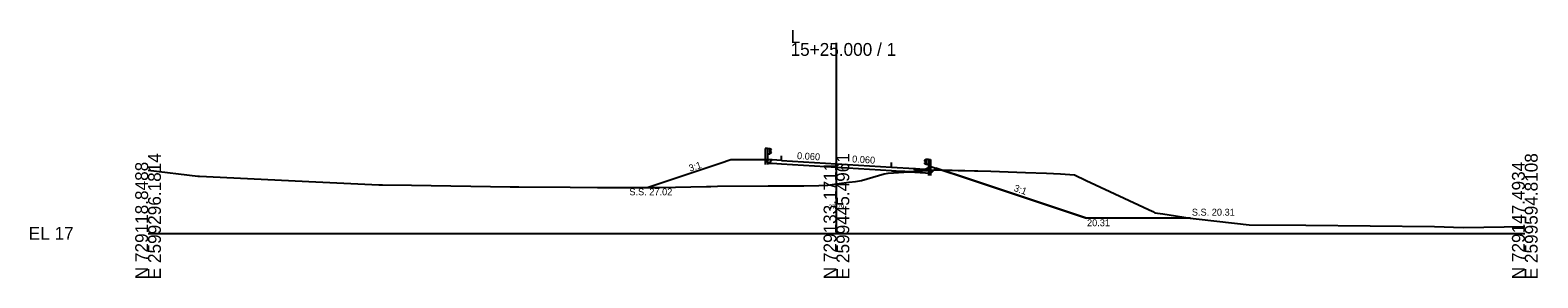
# Model space of a CAD drawing. Extents: x -26 to 3303, y -10 to 9555.
# Drawn here: x 974.3 to 1302.8, y 490.3 to 544.3 of the extents above; entities that cross this region are included whole.
import ezdxf

# ---------------------------------------------------------------- set-up
doc = ezdxf.new("R2010")
doc.units = 0
for name, color, linetype in [('Exist Cross Section Cell', 7, 'Continuous'), ('Exist XS Center Line Elevation Label', 7, 'Continuous'), ('Exist XS Ground Line', 7, 'Continuous'), ('Prop XS Ditch Slope Text', 7, 'Continuous'), ('Prop XS Ditch Standard Text', 7, 'Continuous'), ('Prop XS Dump Level', 7, 'Continuous'), ('Prop XS Earthwork Shape', 7, 'Continuous'), ('Prop XS EOT Tick Mark', 7, 'Continuous'), ('Prop XS Finish Grade', 7, 'Continuous'), ('Prop XS Finish Grade Earthwork', 7, 'Continuous'), ('Prop XS Finish Grade Paved Shoulder', 7, 'Continuous'), ('Prop XS Finish Grade Pavement', 7, 'Continuous'), ('Prop XS Pvmt Edge Slope', 7, 'Continuous'), ('Prop XS SE Text', 7, 'Continuous'), ('Prop XS Side Slope Text', 7, 'Continuous'), ('Prop XS SS Elevation Text', 7, 'Continuous'), ('Prop XS Subgrade Earthwork', 7, 'Continuous'), ('Typical Curb CELL', 7, 'Continuous'), ('Typical Guardrail CELL', 7, 'Continuous')]:
    doc.layers.add(name, color=color, linetype=linetype)

msp = doc.modelspace()

# ---------------------------------------------------------------- linework, layer by layer
at = {"layer": 'Exist Cross Section Cell'}
for p, q in [((1150, 500), (1150, 541.5)), ((1000, 500), (1150, 500)), ((1150, 500), (1300, 500))]:
    msp.add_line(p, q, dxfattribs=at)
at = {"layer": 'Exist XS Ground Line'}
msp.add_lwpolyline([(1000, 513.8), (1010.85, 512.5), (1011.23, 512.49), (1027.66, 511.68), (1035.06, 511.29), (1050.25, 510.61), (1051.09, 510.57), (1057.39, 510.53), (1078.88, 510.18), (1080, 510.16), (1080.79, 510.13), (1091.99, 510.06), (1097.91, 510.02), (1098.5, 510.02), (1099.09, 510.02), (1111.52, 510.01), (1121.72, 510.21), (1122.66, 510.25), (1124.1, 510.3), (1135.12, 510.33), (1142.88, 510.33), (1146.13, 510.43), (1148.16, 510.54), (1150, 510.79), (1152.78, 511.18), (1154.12, 511.32), (1155.47, 511.51), (1160.41, 513.01), (1161.26, 513.12), (1164.65, 513.31), (1171.81, 513.83), (1172.37, 513.82), (1183.67, 513.56), (1191.22, 513.25), (1195.75, 513.15), (1198.83, 512.97), (1201.84, 512.76), (1204.4, 511.56), (1218.92, 504.74), (1219.4, 504.5), (1221.09, 504.23), (1227.1, 503.31), (1229.04, 503.08), (1239.92, 501.85), (1252.31, 501.78), (1280.31, 501.51), (1286.58, 501.25), (1300, 501.52)], dxfattribs=at)
at = {"layer": 'Prop XS Dump Level'}
for p, q in [((1138, 515.91), (1150, 515.19)), ((1150, 515.19), (1162, 514.47))]:
    msp.add_line(p, q, dxfattribs=at)
at = {"layer": 'Prop XS Earthwork Shape'}
for points in [[(1135.21, 515.25), (1134.43, 516.03), (1127, 516.03), (1124.64, 515.25), (1108.95, 510.01), (1111.52, 510.01), (1121.72, 510.21), (1122.66, 510.25), (1124.1, 510.3), (1135.12, 510.33), (1142.88, 510.33), (1146.13, 510.43), (1148.16, 510.54), (1150, 510.79), (1152.78, 511.18), (1154.12, 511.32), (1155.47, 511.51), (1160.41, 513.01), (1161.26, 513.12), (1164.65, 513.31), (1165.9, 513.4), (1164.89, 513.47), (1164, 513.52), (1162, 513.64), (1150, 514.36), (1138, 515.08), (1136, 515.2)], [(1135.21, 515.25), (1134.43, 516.03), (1127, 516.03), (1124.64, 515.25), (1108.95, 510.01), (1111.52, 510.01), (1121.72, 510.21), (1122.66, 510.25), (1124.1, 510.3), (1135.12, 510.33), (1142.88, 510.33), (1146.13, 510.43), (1148.16, 510.54), (1150, 510.79), (1152.78, 511.18), (1154.12, 511.32), (1155.47, 511.51), (1160.41, 513.01), (1161.26, 513.12), (1164.65, 513.31), (1165.9, 513.4), (1164.89, 513.47), (1164, 513.52), (1162, 513.64), (1150, 514.36), (1138, 515.08), (1136, 515.2)], [(1165.9, 513.4), (1170.56, 513.12), (1171.23, 513.79)], [(1165.9, 513.4), (1170.56, 513.12), (1171.23, 513.79)], [(1171.81, 513.83), (1172.37, 513.82), (1172.97, 513.81), (1171.68, 514.24), (1171.23, 513.79)], [(1171.81, 513.83), (1172.37, 513.82), (1172.97, 513.81), (1171.68, 514.24), (1171.23, 513.79)], [(1227.13, 503.31), (1204.46, 503.31), (1176.4, 512.66), (1172.97, 513.81), (1183.67, 513.56), (1191.22, 513.25), (1195.75, 513.15), (1198.83, 512.97), (1201.84, 512.76), (1204.4, 511.56), (1218.92, 504.74), (1219.4, 504.5), (1221.09, 504.23), (1227.1, 503.31)], [(1227.13, 503.31), (1204.46, 503.31), (1176.4, 512.66), (1172.97, 513.81), (1183.67, 513.56), (1191.22, 513.25), (1195.75, 513.15), (1198.83, 512.97), (1201.84, 512.76), (1204.4, 511.56), (1218.92, 504.74), (1219.4, 504.5), (1221.09, 504.23), (1227.1, 503.31)]]:
    msp.add_lwpolyline(points, close=True, dxfattribs=at)
at = {"layer": 'Prop XS EOT Tick Mark'}
for p, q in [((1138, 515.91), (1138, 516.91)), ((1162, 514.47), (1162, 515.47))]:
    msp.add_line(p, q, dxfattribs=at)
at = {"layer": 'Prop XS Finish Grade'}
for p, q in [((1136, 516.03), (1134.43, 516.03)), ((1170.03, 514.36), (1170.56, 514.61)), ((1170.56, 514.61), (1171.68, 514.24))]:
    msp.add_line(p, q, dxfattribs=at)
at = {"layer": 'Prop XS Finish Grade Earthwork'}
for p, q in [((1127, 516.03), (1124.64, 515.25)), ((1134.43, 516.03), (1127, 516.03)), ((1124.64, 515.25), (1108.95, 510.01)), ((1171.68, 514.24), (1176.4, 512.66)), ((1176.4, 512.66), (1204.46, 503.31)), ((1227.13, 503.31), (1204.46, 503.31))]:
    msp.add_line(p, q, dxfattribs=at)
at = {"layer": 'Prop XS Finish Grade Paved Shoulder'}
for p, q in [((1138, 515.91), (1136, 516.03)), ((1162, 514.47), (1167, 514.17))]:
    msp.add_line(p, q, dxfattribs=at)
at = {"layer": 'Prop XS Finish Grade Pavement'}
for p, q in [((1138, 515.91), (1150, 515.19)), ((1150, 515.19), (1162, 514.47))]:
    msp.add_line(p, q, dxfattribs=at)
at = {"layer": 'Prop XS Pvmt Edge Slope'}
for p, q in [((1135.21, 515.25), (1134.43, 516.03)), ((1136, 516.03), (1135.21, 515.25)), ((1170.01, 513.68), (1170.56, 513.12)), ((1170.56, 513.12), (1171.68, 514.24))]:
    msp.add_line(p, q, dxfattribs=at)
at = {"layer": 'Prop XS Subgrade Earthwork'}
for p, q in [((1135.21, 515.25), (1134.43, 516.03)), ((1136, 515.2), (1135.21, 515.25)), ((1138, 515.08), (1136, 515.2)), ((1150, 514.36), (1138, 515.08)), ((1162, 513.64), (1150, 514.36)), ((1162, 513.64), (1164, 513.52)), ((1164, 513.52), (1164.89, 513.47)), ((1164.89, 513.47), (1170.56, 513.12)), ((1170.56, 513.12), (1171.68, 514.24))]:
    msp.add_line(p, q, dxfattribs=at)
at = {"layer": 'Typical Curb CELL'}
for p, q in [((1166.99, 513.76), (1167, 514.16)), ((1170.01, 513.68), (1166.99, 513.76)), ((1167, 514.17), (1167, 514.17)), ((1167.01, 514.17), (1169.33, 514.03)), ((1167.23, 513.9), (1167.32, 514.02)), ((1167.35, 513.9), (1167.23, 513.9)), ((1167.32, 514.02), (1167.35, 513.9)), ((1167.99, 513.83), (1168.06, 513.94)), ((1168.16, 513.87), (1167.99, 513.83)), ((1168.06, 513.94), (1168.16, 513.87)), ((1168.48, 513.87), (1168.57, 513.99)), ((1168.6, 513.87), (1168.48, 513.87)), ((1168.57, 513.99), (1168.6, 513.87)), ((1169.24, 513.8), (1169.31, 513.91)), ((1169.41, 513.84), (1169.24, 513.8)), ((1169.31, 513.91), (1169.41, 513.84)), ((1169.33, 514.03), (1170.03, 514.36)), ((1169.83, 514.03), (1169.84, 513.94)), ((1169.98, 513.98), (1169.83, 514.03)), ((1169.84, 513.94), (1169.98, 513.98)), ((1170.01, 513.68), (1170.03, 514.36))]:
    msp.add_line(p, q, dxfattribs=at)
for centre in [(1167.09, 513.99), (1167.13, 514.12), (1167.49, 514.03), (1167.55, 513.85), (1167.6, 513.82), (1167.64, 513.94), (1167.71, 513.94), (1167.76, 513.97), (1167.81, 513.85), (1168, 513.89), (1168.21, 513.86), (1168.23, 513.91), (1168.24, 513.97), (1168.29, 513.83), (1168.39, 513.87), (1168.48, 513.88), (1168.6, 513.83), (1168.8, 513.82), (1168.85, 513.79), (1168.89, 513.91), (1169.01, 513.94), (1169.06, 513.82), (1169.25, 513.85), (1169.28, 513.75), (1169.46, 513.83), (1169.48, 513.88), (1169.73, 513.85), (1169.85, 513.79), (1169.95, 514.07)]:
    msp.add_circle(centre, 0.00802, dxfattribs=at)
msp.add_arc((1167.01, 514.16), 0.0104, 86.5213, 178.5693, dxfattribs=at)
at = {"layer": 'Typical Guardrail CELL'}
for p, q in [((1135, 518.52), (1134.5, 518.52)), ((1134.5, 518.52), (1134.5, 516.03)), ((1135, 516.03), (1134.5, 516.03)), ((1134.5, 516.03), (1134.5, 515.02)), ((1135, 518.52), (1135, 516.03)), ((1135, 518.52), (1135.5, 518.52)), ((1135, 517.36), (1135.5, 517.36)), ((1135, 516.03), (1135, 515.02)), ((1135.5, 518.52), (1135.5, 517.36)), ((1135.5, 518.52), (1135.79, 518.31)), ((1135.5, 517.98), (1135.79, 518.19)), ((1135.5, 517.94), (1135.5, 517.98)), ((1135.5, 517.94), (1135.5, 517.89)), ((1135.5, 517.89), (1135.79, 517.69)), ((1135.5, 517.36), (1135.79, 517.56)), ((1169.53, 516.14), (1169.24, 515.94)), ((1169.53, 515.61), (1169.24, 515.81)), ((1170.03, 516.14), (1169.53, 516.14)), ((1169.53, 516.14), (1169.53, 514.98)), ((1170.03, 516.14), (1170.03, 513.65)), ((1170.03, 516.14), (1170.53, 516.14)), ((1170.53, 516.14), (1170.53, 513.65)), ((1169.53, 515.51), (1169.24, 515.31)), ((1169.53, 514.98), (1169.24, 515.18)), ((1169.53, 515.56), (1169.53, 515.61)), ((1169.53, 515.56), (1169.53, 515.51)), ((1170.03, 514.98), (1169.53, 514.98)), ((1170.03, 513.65), (1170.53, 513.65)), ((1170.03, 513.65), (1170.03, 512.64)), ((1170.53, 513.65), (1170.53, 512.64))]:
    msp.add_line(p, q, dxfattribs=at)
for centre, start, end in [((1135.74, 518.25), 304.9888, 54.997), ((1135.74, 517.62), 304.9634, 54.9941), ((1169.29, 515.87), 125.003, 235.0112), ((1169.29, 515.25), 125.0059, 235.0366)]:
    msp.add_arc(centre, 0.0776, start, end, dxfattribs=at)

# ---------------------------------------------------------------- texts
at = {"layer": 'Exist Cross Section Cell'}
for s, p in [('L', (1140, 541.5)), ('15+25.000 / 1', (1140, 538.7)), ('EL 17', (974, 498.6))]:
    msp.add_text(s, height=2.8, dxfattribs=at).set_placement(p)
for s, p in [('E 2599296.1814', (1002.8, 490)), ('E 2599445.4961', (1152.8, 490)), ('E 2599594.8108', (1302.8, 490)), ('N 729118.8488', (1000, 490)), ('N 729133.1711', (1150, 490)), ('N 729147.4934', (1300, 490))]:
    msp.add_text(s, height=2.8, rotation=90, dxfattribs=at).set_placement(p)
at = {"layer": 'Exist XS Center Line Elevation Label'}
msp.add_text('27.79', height=1, dxfattribs=at).set_placement((1148.26, 505.29))
at = {"layer": 'Prop XS Ditch Slope Text'}
msp.add_text('3:1', height=1.5, rotation=340.5558, dxfattribs=at).set_placement((1188.54, 509.29))
at = {"layer": 'Prop XS Ditch Standard Text'}
msp.add_text('20.31', height=1.5, dxfattribs=at).set_placement((1204.6, 501.56))
at = {"layer": 'Prop XS Dump Level'}
for p in [(1130, 515.99), (1170, 513.83), (1173, 513.59)]:
    msp.add_text('Case1', height=0.04, dxfattribs=at).set_placement(p)
at = {"layer": 'Prop XS SE Text'}
for p in [(1141.38, 516.21), (1153.38, 515.49)]:
    msp.add_text('0.060', height=1.5, rotation=356.5664, dxfattribs=at).set_placement(p)
at = {"layer": 'Prop XS Side Slope Text'}
msp.add_text('3:1', height=1.5, rotation=18.4349, dxfattribs=at).set_placement((1118.11, 513.43))
at = {"layer": 'Prop XS SS Elevation Text'}
for s, p in [('S.S. 27.02', (1104.87, 508.31)), ('S.S. 20.31', (1227.44, 503.87))]:
    msp.add_text(s, height=1.5, dxfattribs=at).set_placement(p)

doc.saveas('drawing.dxf')
